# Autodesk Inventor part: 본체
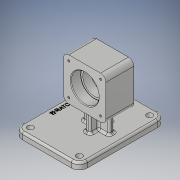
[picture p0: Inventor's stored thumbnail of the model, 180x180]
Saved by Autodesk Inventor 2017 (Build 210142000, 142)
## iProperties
Part Number: 본체
Material: 알루미늄 6061
Document SubType Name: Modeling
Designer: 00-00
Density: 2.7 g/cm^3
Appearance: 알루미늄 - 평지
Mass: 683.576 g
Surface Area: 544.314 cm^2
Volume: 253.176 cm^3
Author: 00-00
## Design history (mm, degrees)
sketch "스케치1"
  geometry: L1 (32, -32)-(-32, -32); L2 (-32, -32)-(-32, 32); L3 (-32, 32)-(32, 32); L4 (32, 32)-(32, -32); L5 (32, -32)-(-32, 32); L6 (-32, -32)-(32, 32); 1 further point
  constraints: 12 end point, 2 midpoint, 2 parallel, 1 horizontal, 1 perpendicular
  dimensions: "d0" = 64 distance of L2.end L3.end; "d1" = 64 distance of L3.end L1.start
extrude "돌출1" new body sketch "스케치1" stored distance "d2" = 42; taper "d3" = 0 deg
node "작업 평면1"
sketch "스케치2"
  geometry: 1 further point
fillet "모깎기1" dims "d5" = 8
sketch "스케치3"
  geometry: L1 (28, 17)-(20, 17); L2 (20, 17)-(20, 25); L3 (20, 25)-(28, 25); L4 (28, 25)-(28, 17); L5 (28, 17)-(20, 25); L6 (20, 17)-(28, 25); 1 further point
  constraints: 12 end point, 2 midpoint, 2 parallel, 1 horizontal, 1 perpendicular
  dimensions: "d6" = 8 distance of L2.end L3.end; "d7" = 8 distance of L3.end L1.start
extrude "돌출2" join sketch "스케치3" distance "d8" = 28; taper "d9" = 0 deg
sketch "스케치4"
  geometry: 1 further point
sketch "스케치5"
  geometry: L1 (36, -65)-(-62, -65); L2 (-62, -65)-(-62, 65); L3 (-62, 65)-(36, 65); L4 (36, 65)-(36, -65); 1 further point
  constraints: 8 end point, 2 parallel, 1 horizontal, 1 perpendicular
  dimensions: "d10" = 98 distance of L1.start L1.end; "d11" = 130 distance of L1.end L2.end; "d15" = 62 distance from line of L2 point (0, 0); "d16" = 65 distance from line of L3 point (0, 0)
extrude "돌출3" join sketch "스케치5" distance "d17" = 10; taper "d18" = 0 deg
sketch "스케치7"
  geometry: L1 (20, -36.719)-(20, -60); L2 (-20, -37)-(-20, -60); L3 (36, -60)-(-62, -60) reference; 1 further point
  constraints: 4 end point, 2 point on line, 2 vertical
  dimensions: "d19" = 20 distance from line of point (0, 0) L2; "d20" = 20 distance from line of point (0, 0) L1
feature "리브1" dims "d21" = 1, "d22" = 8, "d23" = 0, "d24" = 0, "d25" = 1, "d26" = 1
feature "리브2" dims "d27" = 1, "d28" = 8, "d29" = 0, "d30" = 0, "d31" = 1, "d32" = 1
sketch "스케치8"
  geometry: L1 (-37, -17)-(-60, -17); L2 (-35, 17)-(-60, 17); L3 (-60, -65)-(-60, 65) reference; 1 further point
  constraints: 4 end point, 2 horizontal, 2 point on line
  dimensions: "d33" = 17 distance from line of point (0, 0) L2; "d34" = 17 distance from line of point (0, 0) L1
feature "리브3" dims "d35" = 1, "d36" = 8, "d37" = 0, "d38" = 0, "d39" = 1, "d40" = 1
feature "리브4" dims "d41" = 1, "d42" = 8, "d43" = 0, "d44" = 0, "d45" = 1, "d46" = 1
fillet "모깎기2" dims "d47" = 3
fillet "모깎기3" dims "d48" = 3
fillet "모깎기4" dims "d49" = 3
fillet "모깎기5" dims "d50" = 12
fillet "모깎기6" dims "d51" = 3
sketch "스케치9"
  geometry: L1 (17, 7)-(7, 7) reference; L2 (23, -1)-(23, 1) reference; L3 (7, -7)-(17, -7) reference; L4 (7, -14)-(7, -7) reference; L5 (-1, -20)-(1, -20) reference; L6 (-7, -7)-(-7, -14) reference; L7 (-17, -7)-(-7, -7) reference; L8 (-23, 1)-(-23, -1) reference; L9 (-7, 7)-(-17, 7) reference; L10 (-7, 14)-(-7, 7) reference; L11 (1, 20)-(-1, 20) reference; L12 (7, 7)-(7, 14) reference; L13 (33, 53)-(33, -53) reference; L14 (-50, 62)-(24, 62) reference; L15 (-59, -53)-(-59, 53) reference; L16 (24, -62)-(-50, -62) reference; C1 r 4.5 at (-50, -53); C2 r 4.5 at (-50, 53); C3 r 4.5 at (24, 53); C4 r 4.5 at (24, -53); A1 r 6 centre (17, 1) between (23, 1) and (17, 7) reference; A2 r 6 centre (17, -1) between (17, -7) and (23, -1) reference; A3 r 6 centre (1, -14) between (1, -20) and (7, -14) reference; A4 r 6 centre (-1, -14) between (-7, -14) and (-1, -20) reference; A5 r 6 centre (-17, -1) between (-23, -1) and (-17, -7) reference; A6 r 6 centre (-17, 1) between (-17, 7) and (-23, 1) reference; A7 r 6 centre (-1, 14) between (-1, 20) and (-7, 14) reference; A8 r 6 centre (1, 14) between (7, 14) and (1, 20) reference; A9 r 9 centre (24, 53) between (33, 53) and (24, 62) reference; A10 r 9 centre (-50, 53) between (-50, 62) and (-59, 53) reference; A11 r 9 centre (-50, -53) between (-59, -53) and (-50, -62) reference; A12 r 9 centre (24, -53) between (24, -62) and (33, -53) reference; 1 further point
  constraints: 4 centre point, 4 coincident
  dimensions: "d52" = 9 diameter of C1; "d53" = 9 diameter of C2; "d56" = 9 diameter of C3; "d57" = 9 diameter of C4
  node "투영된 루프1"
extrude "돌출4" cut sketch "스케치9" stored distance "d54" = 10; taper "d55" = 0 deg
extrude "돌출5" cut sketch "스케치9" stored distance "d58" = 10; taper "d59" = 0 deg
sketch "스케치10"
  geometry: L1 (0, 40.5)-(0, -40.5); L2 (21, 21)-(21, 6); L3 (24, 21)-(-24, 21) reference; L4 (21, 6)-(18, 6); L5 (18, 6)-(18, -6); L6 (18, -6)-(21, -6); L7 (21, -6)-(21, -21); L8 (21, 21)-(0, 21); L9 (21, -21)-(0, -21); L10 (-24, -21)-(24, -21) reference; L11 (0, 21)-(0, -21); 2 further points
  constraints: 18 end point, 5 perpendicular, 3 midpoint, 2 point on line, 1 coincident, 1 collinear, 1 vertical
  dimensions: "d60" = 42 diameter of L2 L1; "d61" = 42 diameter of L7 L1; "d62" = 36 diameter of L5 L1; "d63" = 15 distance of L2.start L2.end; "d64" = 15 distance of L6.end L7.end
revolve "회전1" sketch "스케치10" stored, may be unused: angle "d65" = 90 deg
fillet "모깎기7" dims "d66" = 0.3
sketch "스케치11"
  geometry: 5 further points
  dimensions: "d67" = 24 horizontal distance of point (0, 0) point (-24, 24); "d68" = 24 horizontal distance of point (0, 0) point (24, 24); "d69" = 24 horizontal distance of point (0, 0) point (-24, 24); "d70" = 24 horizontal distance of point (0, 0) point (-24, -24); "d71" = 24 horizontal distance of point (0, 0) point (24, 24); "d72" = 24 horizontal distance of point (0, 0) point (24, -24); "d73" = 24 horizontal distance of point (24, -24) point (0, 0); "d74" = 24 horizontal distance of point (0, 0) point (-24, -24)
hole "구멍1" sketch "스케치11" at (24, 24), (-24, 24), (-24, -24), (24, -24) diameter "d75" = 3.242; stored, may be unused: countersink angle "d79" = 90 deg, drill point angle "d81" = 118 deg; dims "d76" = 8, "d77" = 4, "d78" = 2, "d80" = 10
sketch "스케치12"
  geometry: 5 further points
  dimensions: "d82" = 24 horizontal distance of point (0, 0) point (24, 24); "d83" = 24 horizontal distance of point (0, 0) point (-24, 24); "d84" = 24 horizontal distance of point (0, 0) point (-24, -24); "d85" = 24 horizontal distance of point (0, 0) point (-24, 24); "d86" = 24 horizontal distance of point (0, 0) point (-24, -24); "d87" = 24 horizontal distance of point (0, 0) point (24, -24); "d88" = 24 horizontal distance of point (24, -24) point (0, 0); "d89" = 24 horizontal distance of point (0, 0) point (24, 24)
hole "구멍2" sketch "스케치12" at (-24, 24), (24, 24), (24, -24), (-24, -24) diameter "d90" = 3.242; stored, may be unused: countersink angle "d94" = 90 deg, drill point angle "d96" = 118 deg; dims "d91" = 8, "d92" = 4, "d93" = 2, "d95" = 10
sketch "스케치13"
  geometry: L1 (-62, 53)-(-62, -53) reference; L2 (24, 65)-(-50, 65) reference; 2 further points
  constraints: 1 other
  dimensions: "d97" = 10 distance from line of L1 point (-52, 0); "d98" = 65 distance from line of L2 point (-52, 0)
feature "엠보싱1" sketch "스케치13" dims "d0" = 64, "d1" = 64, "d99" = 0.5, "d100" = 0
chamfer "모따기1" distance "d101" = 1; stored, may be unused: second distance "d102" = 2, angle "d103" = 45 deg
node "솔리드1"
